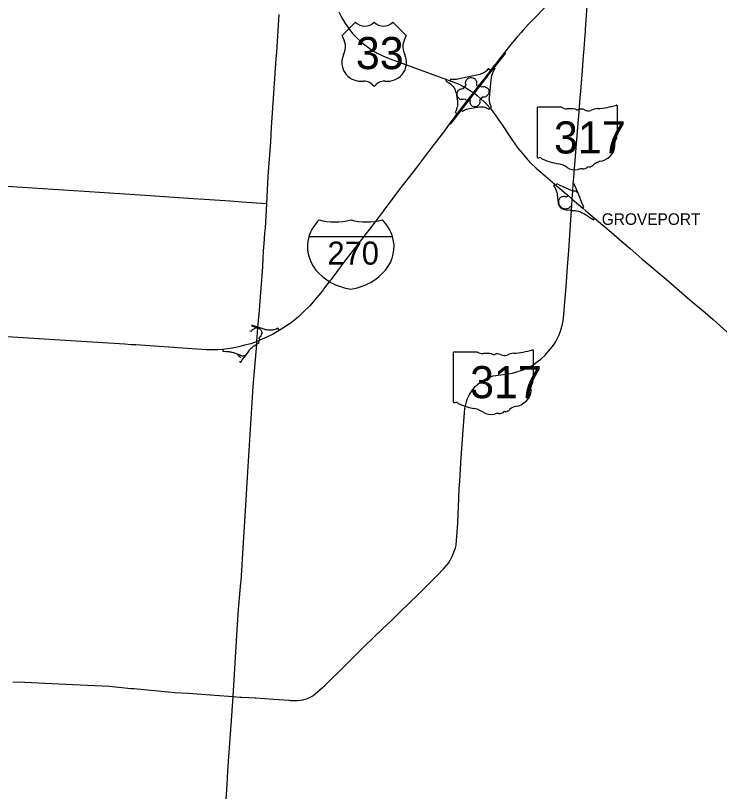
# Model space of a CAD drawing. Extents: x -1146 to -445, y -1283 to -822.
# Drawn here: x -862.8 to -786.6, y -1188.9 to -1104.6 of the extents above; entities that cross this region are included whole.
import ezdxf

# ---------------------------------------------------------------- set-up
doc = ezdxf.new("R2010")
doc.units = 0
for name, color, linetype in [('GM_X_Corporation_Text', 7, 'Continuous'), ('GM_X_Interchange_Ramps', 7, 'Continuous'), ('GM_X_Interstate_Route', 7, 'Continuous'), ('GM_X_Interstate_Shield', 7, 'Continuous'), ('GM_X_State_Route', 7, 'Continuous'), ('GM_X_State_Shield', 7, 'Continuous'), ('GM_X_Township', 7, 'Continuous'), ('GM_X_US_Route', 7, 'Continuous'), ('GM_X_US_Shield', 7, 'Continuous')]:
    doc.layers.add(name, color=color, linetype=linetype)

msp = doc.modelspace()

# ---------------------------------------------------------------- linework, layer by layer
at = {"layer": 'GM_X_Interchange_Ramps'}
for points in [[(-815.755, -1116.238), (-815.666, -1116.305), (-814.538, -1114.844), (-813.657, -1113.702), (-813.113, -1112.993), (-812.492, -1112.192), (-811.272, -1110.612), (-810.936, -1110.185), (-810.719, -1109.91), (-809.747, -1108.674), (-809.865, -1108.581)], [(-811.378, -1110.516), (-811.597, -1110.343), (-811.68, -1110.434), (-811.773, -1110.524), (-811.885, -1110.618), (-811.997, -1110.699), (-812.142, -1110.788), (-812.248, -1110.843), (-812.386, -1110.903), (-812.518, -1110.949), (-812.701, -1110.997), (-814.914, -1111.467), (-815.04, -1111.486), (-815.192, -1111.497), (-815.498, -1111.495), (-815.709, -1111.493), (-815.765, -1111.639)], [(-811.418, -1114.592), (-811.263, -1114.461), (-811.303, -1114.391), (-811.354, -1114.28), (-811.396, -1114.174), (-811.427, -1114.073), (-811.454, -1113.968), (-811.475, -1113.856), (-811.488, -1113.753), (-811.495, -1113.625), (-811.492, -1113.472), (-811.289, -1111.531), (-811.274, -1111.394), (-811.249, -1111.243), (-811.222, -1111.118), (-811.189, -1110.994), (-811.155, -1110.884), (-811.116, -1110.775), (-811.058, -1110.634), (-811.01, -1110.532), (-810.916, -1110.333), (-810.862, -1110.244), (-810.936, -1110.185)], [(-814.183, -1112.324), (-814.011, -1112.128), (-814.044, -1112.02), (-814.059, -1111.93), (-814.06, -1111.832), (-814.044, -1111.731), (-814.007, -1111.624), (-813.963, -1111.546), (-813.887, -1111.453), (-813.811, -1111.388), (-813.721, -1111.336), (-813.64, -1111.304), (-813.55, -1111.284), (-813.431, -1111.279), (-813.291, -1111.304), (-813.202, -1111.34), (-813.116, -1111.391), (-813.036, -1111.461), (-812.979, -1111.529), (-812.935, -1111.601), (-812.895, -1111.699), (-812.875, -1111.788), (-812.869, -1111.883), (-812.893, -1112.116), (-812.721, -1112.254)], [(-816.129, -1111.498), (-816.202, -1111.673), (-816.066, -1111.746), (-815.979, -1111.795), (-815.893, -1111.847), (-815.8, -1111.905), (-815.715, -1111.965), (-815.641, -1112.029), (-815.573, -1112.094), (-815.497, -1112.175), (-815.419, -1112.27), (-815.351, -1112.364), (-815.295, -1112.452), (-815.235, -1112.561), (-815.188, -1112.66), (-815.139, -1112.785), (-815.109, -1112.879), (-815.08, -1112.992), (-815.056, -1113.107), (-815.037, -1113.201), (-815.017, -1113.31), (-814.996, -1113.438), (-814.979, -1113.547), (-814.963, -1113.67), (-814.95, -1113.775), (-814.941, -1113.865), (-814.931, -1113.969), (-814.928, -1114.069), (-814.929, -1114.152), (-814.938, -1114.271), (-814.953, -1114.382), (-814.973, -1114.483), (-814.998, -1114.579), (-815.032, -1114.686), (-815.093, -1114.863), (-815.18, -1115.058), (-814.994, -1115.194)], [(-813.913, -1113.792), (-814.127, -1113.629), (-814.308, -1113.674), (-814.391, -1113.681), (-814.486, -1113.674), (-814.585, -1113.651), (-814.677, -1113.612), (-814.773, -1113.549), (-814.838, -1113.488), (-814.9, -1113.408), (-814.945, -1113.323), (-814.976, -1113.233), (-814.993, -1113.133), (-814.991, -1113.027), (-814.973, -1112.928), (-814.939, -1112.836), (-814.892, -1112.752), (-814.826, -1112.671), (-814.758, -1112.611), (-814.677, -1112.56), (-814.592, -1112.523), (-814.486, -1112.497), (-814.3, -1112.486), (-814.183, -1112.324)], [(-812.492, -1112.192), (-812.373, -1112.287), (-812.212, -1112.247), (-812.116, -1112.241), (-812.021, -1112.25), (-811.895, -1112.287), (-811.783, -1112.35), (-811.717, -1112.405), (-811.659, -1112.469), (-811.602, -1112.56), (-811.557, -1112.674), (-811.538, -1112.79), (-811.541, -1112.895), (-811.56, -1112.99), (-811.595, -1113.082), (-811.649, -1113.173), (-811.709, -1113.243), (-811.794, -1113.313), (-811.879, -1113.361), (-811.99, -1113.399), (-812.092, -1113.414), (-812.255, -1113.412), (-812.399, -1113.583)], [(-812.399, -1113.583), (-812.547, -1113.744), (-812.536, -1113.822), (-812.528, -1113.905), (-812.534, -1113.99), (-812.552, -1114.097), (-812.603, -1114.216), (-812.657, -1114.293), (-812.734, -1114.365), (-812.831, -1114.424), (-812.916, -1114.455), (-813.018, -1114.471), (-813.131, -1114.465), (-813.234, -1114.437), (-813.301, -1114.406), (-813.387, -1114.345), (-813.452, -1114.277), (-813.501, -1114.204), (-813.535, -1114.125), (-813.557, -1114.037), (-813.563, -1113.948), (-813.547, -1113.785), (-813.657, -1113.702)], [(-814.538, -1114.844), (-814.414, -1114.938), (-814.275, -1114.86), (-814.198, -1114.821), (-814.129, -1114.789), (-814.04, -1114.753), (-813.958, -1114.724), (-813.839, -1114.689), (-813.644, -1114.646), (-812.549, -1114.466), (-812.438, -1114.452), (-812.325, -1114.448), (-812.228, -1114.454), (-812.117, -1114.47), (-811.996, -1114.5), (-811.9, -1114.534), (-811.759, -1114.601), (-811.673, -1114.655), (-811.58, -1114.725), (-811.418, -1114.592)], [(-804.392, -1122.842), (-804.539, -1123.004), (-804.438, -1123.143), (-804.379, -1123.238), (-804.322, -1123.343), (-804.282, -1123.428), (-804.245, -1123.519), (-804.211, -1123.62), (-804.184, -1123.719), (-804.157, -1123.85), (-804.14, -1123.983), (-804.046, -1124.892), (-804.014, -1125.012), (-803.975, -1125.104), (-803.932, -1125.182), (-803.868, -1125.273), (-803.788, -1125.36), (-803.723, -1125.416), (-803.643, -1125.471), (-803.562, -1125.516), (-803.489, -1125.546), (-803.394, -1125.574), (-803.306, -1125.589), (-803.188, -1125.608), (-802.71, -1125.654), (-802.61, -1125.661)], [(-802.461, -1123.569), (-802.532, -1123.565), (-803.888, -1122.939), (-804.168, -1122.782), (-804.293, -1122.928)], [(-801.379, -1125.423), (-801.256, -1125.29), (-801.362, -1125.09), (-801.915, -1123.746), (-802.227, -1122.987), (-802.283, -1122.831), (-802.412, -1122.823)], [(-802.579, -1125.253), (-802.714, -1125.243), (-802.762, -1125.309), (-802.825, -1125.374), (-802.892, -1125.426), (-802.96, -1125.465), (-803.026, -1125.494), (-803.091, -1125.513), (-803.182, -1125.528), (-803.269, -1125.53), (-803.354, -1125.52), (-803.446, -1125.495), (-803.593, -1125.416), (-803.694, -1125.346), (-803.78, -1125.265), (-803.856, -1125.167), (-803.904, -1125.083), (-803.937, -1125.007), (-803.969, -1124.899), (-803.985, -1124.789), (-803.986, -1124.674), (-803.964, -1124.552), (-803.934, -1124.475), (-803.898, -1124.409), (-803.853, -1124.348), (-803.778, -1124.274), (-803.703, -1124.221), (-803.614, -1124.179), (-803.528, -1124.154), (-803.443, -1124.143), (-803.347, -1124.146), (-803.267, -1124.161), (-803.205, -1124.181), (-803.117, -1124.22), (-802.965, -1124.065)], [(-801.915, -1123.746), (-801.943, -1123.758), (-801.99, -1123.708), (-802.046, -1123.663), (-802.107, -1123.627), (-802.18, -1123.599), (-802.247, -1123.583), (-802.293, -1123.578), (-802.341, -1123.577), (-802.461, -1123.569)], [(-802.61, -1125.661), (-802.524, -1125.668), (-802.276, -1125.686), (-802.192, -1125.693), (-802.095, -1125.709), (-801.829, -1125.768), (-801.62, -1125.836), (-801.43, -1125.922), (-801.266, -1126.005), (-801.099, -1126.107), (-800.232, -1126.684), (-800.094, -1126.526)], [(-837.429, -1138.702), (-837.259, -1138.761), (-837.184, -1138.657), (-837.116, -1138.572), (-837.048, -1138.518), (-836.988, -1138.48), (-836.874, -1138.422), (-836.762, -1138.398), (-836.668, -1138.392), (-836.545, -1138.413), (-836.465, -1138.435), (-836.346, -1138.499), (-836.277, -1138.566), (-836.224, -1138.636), (-836.188, -1138.703), (-836.158, -1138.778), (-836.136, -1138.877), (-836.131, -1138.975), (-836.146, -1139.089), (-836.179, -1139.189), (-836.221, -1139.269), (-836.295, -1139.354), (-836.359, -1139.413), (-836.429, -1139.466), (-836.326, -1139.733)], [(-837.235, -1138.166), (-837.149, -1138.194), (-836.766, -1138.318), (-836.762, -1138.398)], [(-834.235, -1138.672), (-834.387, -1138.441), (-834.484, -1138.485), (-834.582, -1138.526), (-834.691, -1138.564), (-834.791, -1138.593), (-834.898, -1138.616), (-834.988, -1138.631), (-835.104, -1138.644), (-835.227, -1138.65), (-835.349, -1138.647), (-835.481, -1138.635), (-835.604, -1138.616), (-835.726, -1138.588), (-835.875, -1138.542), (-836.547, -1138.324), (-837.13, -1138.136), (-837.211, -1138.107)], [(-838.578, -1142.049), (-838.412, -1142.112), (-838.338, -1141.989), (-838.246, -1141.854), (-838.074, -1141.628), (-837.868, -1141.393), (-837.47, -1140.809), (-837.413, -1140.744), (-837.336, -1140.663), (-837.259, -1140.586), (-837.185, -1140.517), (-837.1, -1140.442), (-837.023, -1140.379), (-836.95, -1140.322), (-836.854, -1140.252), (-836.68, -1140.139), (-836.605, -1140.094), (-836.514, -1140.044), (-836.414, -1139.993), (-836.489, -1139.8)], [(-840.346, -1140.727), (-840.33, -1140.917), (-839.945, -1140.936), (-839.853, -1140.941), (-839.754, -1140.949), (-839.658, -1140.961), (-839.576, -1140.974), (-839.484, -1140.991), (-839.409, -1141.008), (-839.318, -1141.032), (-839.198, -1141.066), (-839.089, -1141.102), (-838.984, -1141.137), (-838.844, -1141.205), (-838.793, -1141.229), (-838.746, -1141.261), (-838.71, -1141.295), (-838.68, -1141.326), (-838.649, -1141.37), (-838.621, -1141.424), (-838.595, -1141.477), (-838.409, -1141.553)], [(-838.844, -1141.205), (-838.838, -1141.187), (-838.496, -1141.298), (-838.347, -1141.377)], [(-838.347, -1141.377), (-838.255, -1141.403), (-838.161, -1141.426), (-838.097, -1141.428), (-838.028, -1141.417), (-837.96, -1141.396), (-837.895, -1141.36), (-837.868, -1141.393)]]:
    msp.add_lwpolyline(points, dxfattribs=at)
at = {"layer": 'GM_X_Interstate_Route'}
for points in [[(-802.193, -1100.582), (-803.442, -1101.758), (-804.597, -1102.868), (-805.506, -1103.728), (-806.515, -1104.793), (-807.247, -1105.509), (-807.849, -1106.161), (-808.05, -1106.398)], [(-808.05, -1106.398), (-808.433, -1106.851), (-809.294, -1107.905), (-809.865, -1108.581)], [(-809.865, -1108.581), (-810.411, -1109.26), (-810.841, -1109.83), (-810.994, -1110.026)], [(-810.994, -1110.026), (-811.378, -1110.516), (-812.094, -1111.457), (-812.721, -1112.254), (-813.213, -1112.917)], [(-813.213, -1112.917), (-813.913, -1113.792), (-814.994, -1115.194), (-815.755, -1116.238)], [(-815.755, -1116.238), (-816.352, -1117.052), (-818.094, -1119.304), (-819.489, -1121.166), (-821.329, -1123.527), (-822.571, -1125.184)], [(-822.96, -1125.704), (-823.204, -1126.03), (-823.963, -1127.051), (-825.848, -1129.473), (-827.14, -1131.139), (-828.438, -1132.89), (-828.662, -1133.186), (-828.711, -1133.251)], [(-822.571, -1125.184), (-822.957, -1125.7), (-822.96, -1125.704)], [(-828.711, -1133.251), (-829.436, -1134.207), (-829.496, -1134.286)], [(-829.496, -1134.286), (-829.599, -1134.422), (-830.94, -1135.992), (-831.667, -1136.728), (-832.098, -1137.141), (-832.123, -1137.163)], [(-850.255, -1140.217), (-850.957, -1140.159), (-856.794, -1139.812), (-863.126, -1139.382), (-866.131, -1139.196), (-870.172, -1138.941), (-873.251, -1138.719), (-876.652, -1138.518), (-877.807, -1138.452), (-880.683, -1138.232), (-881.301, -1138.185), (-883.025, -1138.058), (-883.999, -1137.894), (-884.369, -1137.831), (-885.679, -1137.562)], [(-832.123, -1137.163), (-832.547, -1137.535), (-833.061, -1137.911), (-834.235, -1138.672), (-834.976, -1139.11), (-835.825, -1139.506), (-836.326, -1139.733), (-836.489, -1139.8), (-836.654, -1139.868), (-836.712, -1139.892)], [(-836.712, -1139.892), (-836.732, -1139.9), (-837.318, -1140.109), (-837.985, -1140.276)], [(-837.985, -1140.276), (-838.609, -1140.436), (-839.313, -1140.584), (-840.346, -1140.727), (-840.931, -1140.762), (-842.101, -1140.781), (-843.679, -1140.66), (-849.762, -1140.246), (-850.126, -1140.227), (-850.255, -1140.217)]]:
    msp.add_lwpolyline(points, dxfattribs=at)
at = {"layer": 'GM_X_Interstate_Shield'}
msp.add_line((-821.965, -1128.54), (-831.03, -1128.54), dxfattribs=at)
msp.add_line((-821.965, -1128.54), (-831.03, -1128.54), dxfattribs=at)
for centre, start_param, end_param in [((-825.325, -1129.611), 2.47259, 2.911027), ((-828.21, -1122.221), 4.415841, 5.008937), ((-824.785, -1122.221), 4.415841, 5.008937), ((-827.669, -1129.611), 0.230566, 0.669003), ((-825.325, -1129.611), 2.911027, 4.511031), ((-827.669, -1129.611), 4.913747, 6.513751)]:
    msp.add_ellipse(centre, major_axis=(5.859, 0), ratio=0.8, start_param=start_param, end_param=end_param, dxfattribs=at)
at = {"layer": 'GM_X_State_Route'}
for points in [[(-801.078, -1106.07), (-800.916, -1103.575)], [(-801.64, -1113.153), (-801.462, -1111.026), (-801.296, -1108.938), (-801.246, -1108.174), (-801.205, -1107.671), (-801.17, -1107.183), (-801.13, -1106.705), (-801.09, -1106.252), (-801.078, -1106.07)], [(-801.662, -1113.415), (-801.64, -1113.153)], [(-802.351, -1122.148), (-802.26, -1121.145), (-801.882, -1116.235), (-801.775, -1114.99), (-801.7, -1113.94)], [(-801.7, -1113.94), (-801.668, -1113.485), (-801.662, -1113.415)], [(-802.518, -1124.458), (-802.461, -1123.569), (-802.412, -1122.823), (-802.375, -1122.418)], [(-802.375, -1122.418), (-802.351, -1122.148)], [(-802.6, -1125.525), (-802.579, -1125.253), (-802.518, -1124.458)], [(-802.682, -1126.685), (-802.61, -1125.661), (-802.6, -1125.525)], [(-813.98, -1146.405), (-813.875, -1146.045), (-813.695, -1145.664), (-813.404, -1145.202), (-813.033, -1144.741), (-812.513, -1144.292), (-812.242, -1144.114), (-811.859, -1143.9), (-811.37, -1143.687), (-811.094, -1143.594), (-810.795, -1143.534), (-809.45, -1143.376), (-808.979, -1143.286), (-808.618, -1143.206), (-807.945, -1142.985), (-807.363, -1142.724), (-806.802, -1142.413), (-806.276, -1142.051), (-805.921, -1141.78), (-805.455, -1141.346), (-805.086, -1140.913), (-804.666, -1140.394), (-804.329, -1139.929), (-804.142, -1139.573), (-803.947, -1139.153), (-803.779, -1138.732), (-803.569, -1137.994), (-803.498, -1137.649), (-803.463, -1137.296), (-803.381, -1136.509), (-803.275, -1135.158), (-803.193, -1133.937), (-803.017, -1131.787), (-802.886, -1130.019), (-802.682, -1126.685)], [(-814.698, -1154.996), (-814.567, -1153.003), (-814.354, -1149.928), (-814.138, -1147.123), (-814.019, -1146.536), (-813.98, -1146.405)], [(-814.8, -1156.969), (-814.783, -1156.699), (-814.756, -1155.835), (-814.698, -1154.996)], [(-818.125, -1166.176), (-817.157, -1165.201), (-816.425, -1164.446), (-815.916, -1163.855), (-815.573, -1163.295), (-815.393, -1162.846), (-815.168, -1162.191), (-815.102, -1161.908), (-815.036, -1161.403), (-814.915, -1159.555), (-814.841, -1157.616), (-814.804, -1157.027), (-814.8, -1156.969)], [(-818.597, -1166.648), (-818.404, -1166.456), (-818.125, -1166.176)], [(-833.008, -1178.725), (-832.309, -1178.745), (-831.977, -1178.713), (-831.672, -1178.66), (-831.42, -1178.591), (-831.172, -1178.515), (-830.874, -1178.385), (-830.592, -1178.229), (-829.3, -1177.117), (-827.136, -1174.979), (-825.056, -1172.91), (-823.028, -1170.952), (-822.152, -1170.134), (-821.025, -1169.034), (-819.282, -1167.325), (-818.597, -1166.648)], [(-863.071, -1176.712), (-861.792, -1176.766), (-857.366, -1176.969)], [(-857.366, -1176.969), (-852.602, -1177.188), (-850.291, -1177.424), (-849.99, -1177.453)], [(-849.99, -1177.453), (-845.915, -1177.843), (-845.578, -1177.864), (-845.523, -1177.867)], [(-845.523, -1177.867), (-844.046, -1177.957), (-841.213, -1178.153), (-841.203, -1178.154)], [(-841.203, -1178.154), (-839.213, -1178.312), (-838.456, -1178.365), (-838.316, -1178.37)], [(-838.316, -1178.37), (-837.539, -1178.403), (-836.852, -1178.459), (-836.779, -1178.463)], [(-836.779, -1178.463), (-834.815, -1178.592), (-833.133, -1178.721), (-833.008, -1178.725)]]:
    msp.add_lwpolyline(points, dxfattribs=at)
at = {"layer": 'GM_X_State_Shield'}
for p, q in [((-806.322, -1114.597), (-806.322, -1119.88)), ((-803.689, -1114.506), (-806.237, -1114.506)), ((-797.621, -1117.139), (-797.621, -1114.375)), ((-797.622, -1117.138), (-797.621, -1117.139)), ((-806.698, -1143.639), (-806.698, -1140.875)), ((-815.399, -1141.097), (-815.399, -1146.38)), ((-812.766, -1141.006), (-815.314, -1141.006)), ((-806.699, -1143.638), (-806.698, -1143.639))]:
    msp.add_line(p, q, dxfattribs=at)
for centre, major_axis, start_param, end_param in [((-806.223, -1114.586), (0.101, 0), 1.712693, 3.28349), ((-803.082, -1113.893), (0.978, 0), 4.042523, 4.731795), ((-802.758, -1117.472), (3.51, 0), 1.404758, 1.657858), ((-801.961, -1114.559), (0.282, 0), 3.836095, 5.185415), ((-801.547, -1115.169), (0.586, 0), 0.950623, 2.079405), ((-800.79, -1114.332), (0.705, 0), 4.081561, 5.145723), ((-799.544, -1116.12), (1.856, 0), 1.699011, 2.107814), ((-800.721, -1107.304), (9.227, 0), 4.814394, 5.042369), ((-797.718, -1114.364), (0.0969, 0), 6.141152, 7.989035), ((-797.644, -1117.342), (0.15, 0), 1.883978, 3.671073), ((-797.725, -1117.15), (0.104, 0), 5.05454, 6.418171), ((-797.274, -1118.296), (0.655, 0), 2.387724, 3.262537), ((-798.597, -1117.691), (0.9, 0), 5.934695, 6.695948), ((-800.204, -1118.647), (2.308, 0), 5.101752, 6.440018), ((-806.222, -1119.892), (0.102, 0), 3.00124, 4.508301), ((-806.206, -1119.351), (0.776, 0), 4.665946, 4.897461), ((-806.048, -1120.185), (0.28, 0), 0.519207, 1.627899), ((-802.515, -1115.438), (6.663, 0), 4.195997, 4.488961), ((-804.501, -1122.254), (2.085, 0), 0.823519, 1.323587), ((-800.832, -1120.392), (0.746, 0), 4.937069, 5.64225), ((-799.231, -1121.364), (1.264, 0), 1.647645, 2.488434), ((-802.246, -1120.211), (1.323, 0), 4.026481, 4.996735), ((-801.482, -1122.038), (1.087, 0), 1.495662, 1.94098), ((-801.385, -1120.607), (0.705, 0), 4.691044, 5.507374), ((-800.748, -1121.119), (0.198, 0), 1.147584, 2.315152), ((-809.798, -1133.803), (9.227, 0), 4.814394, 5.042369), ((-806.795, -1140.864), (0.0969, 0), 6.141152, 7.989035), ((-815.3, -1141.086), (0.101, 0), 1.712693, 3.28349), ((-812.159, -1140.393), (0.978, 0), 4.042523, 4.731795), ((-811.835, -1143.972), (3.51, 0), 1.404758, 1.657858), ((-811.038, -1141.058), (0.282, 0), 3.836095, 5.185415), ((-810.624, -1141.669), (0.586, 0), 0.950623, 2.079405), ((-809.867, -1140.831), (0.705, 0), 4.081561, 5.145723), ((-808.621, -1142.62), (1.856, 0), 1.699011, 2.107814), ((-806.721, -1143.842), (0.15, 0), 1.883978, 3.671073), ((-807.674, -1144.191), (0.9, 0), 5.934695, 6.695948), ((-806.802, -1143.649), (0.104, 0), 5.05454, 6.418171), ((-809.281, -1145.147), (2.308, 0), 5.101752, 6.440018), ((-806.351, -1144.795), (0.655, 0), 2.387724, 3.262537), ((-815.299, -1146.392), (0.102, 0), 3.00124, 4.508301), ((-815.283, -1145.851), (0.776, 0), 4.665946, 4.897461), ((-815.125, -1146.685), (0.28, 0), 0.519207, 1.627899), ((-811.592, -1141.938), (6.663, 0), 4.195997, 4.488961), ((-808.308, -1147.863), (1.264, 0), 1.647645, 2.488434), ((-813.578, -1148.754), (2.085, 0), 0.823519, 1.323587), ((-811.323, -1146.711), (1.323, 0), 4.026481, 4.996735), ((-810.559, -1148.538), (1.087, 0), 1.495662, 1.94098), ((-810.462, -1147.107), (0.705, 0), 4.691044, 5.507374), ((-809.825, -1147.618), (0.198, 0), 1.147584, 2.315152), ((-809.909, -1146.892), (0.746, 0), 4.937069, 5.64225)]:
    msp.add_ellipse(centre, major_axis=major_axis, ratio=0.8, start_param=start_param, end_param=end_param, dxfattribs=at)
at = {"layer": 'GM_X_Township'}
for points in [[(-839.986, -1189.404), (-839.888, -1187.914), (-839.788, -1186.397), (-839.683, -1184.799), (-839.589, -1183.374), (-839.458, -1181.394), (-839.213, -1178.312), (-838.817, -1171.67), (-838.631, -1168.836), (-838.386, -1166.005), (-838.375, -1165.843), (-838.093, -1161.622), (-837.883, -1158.186), (-837.65, -1153.964), (-837.042, -1144.742), (-836.68, -1140.139), (-836.654, -1139.868), (-836.545, -1138.413), (-836.547, -1138.324), (-836.376, -1136.537), (-836.345, -1135.972), (-836.011, -1131.781), (-835.936, -1130.045), (-835.887, -1129.24), (-835.789, -1128.143), (-835.735, -1127.555), (-835.589, -1125.008), (-835.585, -1124.955), (-835.431, -1121.964), (-835.159, -1118.245), (-835.078, -1116.687), (-834.556, -1109.269), (-834.503, -1108.493), (-834.261, -1104.464)], [(-835.589, -1125.008), (-835.585, -1124.955), (-835.644, -1124.951), (-838.263, -1124.769), (-839.555, -1124.672), (-842.354, -1124.475), (-843.569, -1124.413), (-848.745, -1124.067), (-855.341, -1123.619), (-862.055, -1123.177), (-864.742, -1123.001), (-866.693, -1122.873), (-866.806, -1122.867), (-870.047, -1122.655), (-871.799, -1122.523), (-874.423, -1122.339), (-875.436, -1122.275), (-877.054, -1122.178), (-878.503, -1122.082), (-879.46, -1122.01), (-882.142, -1121.871), (-887.957, -1121.659)]]:
    msp.add_lwpolyline(points, dxfattribs=at)
at = {"layer": 'GM_X_US_Route'}
for points in [[(-827.794, -1104.163), (-827.57, -1104.623), (-827.356, -1105.011), (-827.11, -1105.419), (-826.741, -1105.935), (-826.253, -1106.547), (-825.856, -1106.966), (-825.472, -1107.333), (-824.986, -1107.748), (-824.239, -1108.279), (-823.621, -1108.644), (-823.022, -1108.945), (-822.531, -1109.149), (-821.937, -1109.377), (-819.762, -1110.169), (-817.898, -1110.853), (-816.129, -1111.498), (-815.765, -1111.639), (-815.622, -1111.686), (-815.15, -1111.861), (-814.875, -1111.977), (-814.595, -1112.11), (-814.35, -1112.235), (-814.183, -1112.324), (-814.031, -1112.413), (-813.667, -1112.629), (-813.426, -1112.781)], [(-813.426, -1112.781), (-813.213, -1112.917), (-813.113, -1112.993), (-812.813, -1113.234), (-812.399, -1113.583), (-812.052, -1113.912), (-811.739, -1114.24), (-811.418, -1114.592), (-811.061, -1115.059), (-810.776, -1115.436), (-810.031, -1116.534), (-809.195, -1117.772), (-808.403, -1118.918), (-807.918, -1119.523), (-807.405, -1120.12), (-806.967, -1120.58), (-806.412, -1121.111), (-804.392, -1122.842), (-804.293, -1122.928), (-802.965, -1124.065), (-802.518, -1124.458)], [(-802.518, -1124.458), (-801.379, -1125.423), (-801.036, -1125.717)], [(-801.036, -1125.717), (-800.094, -1126.526), (-799.892, -1126.698)], [(-799.892, -1126.698), (-798.321, -1128.034), (-797.134, -1129.056), (-796.265, -1129.799)], [(-796.265, -1129.799), (-794.971, -1130.905), (-792.364, -1133.132), (-790.065, -1135.107), (-789.806, -1135.34), (-789.528, -1135.577), (-788.145, -1136.739), (-787.251, -1137.502), (-785.769, -1138.82), (-785.123, -1139.466), (-784.543, -1140.047), (-783.239, -1141.424), (-782.129, -1142.603), (-781.234, -1143.468), (-780.589, -1143.995), (-780.079, -1144.379), (-779.517, -1144.768), (-778.842, -1145.18), (-774.819, -1147.381), (-770.552, -1149.725), (-770.424, -1149.795)]]:
    msp.add_lwpolyline(points, dxfattribs=at)
at = {"layer": 'GM_X_US_Shield'}
for p, q in [((-825.992, -1105.301), (-827.442, -1106.751)), ((-820.481, -1106.751), (-821.932, -1105.301)), ((-825.412, -1111.681), (-825.122, -1111.681)), ((-822.802, -1111.681), (-822.512, -1111.681))]:
    msp.add_line(p, q, dxfattribs=at)
for centre, radius, start, end in [((-824.977, -1104.265), 1.45, 225.573, 314.427), ((-822.947, -1104.265), 1.45, 225.573, 314.427), ((-829.105, -1107.915), 2.03, 334.54712, 35.00093), ((-818.818, -1107.915), 2.03, 144.99907, 205.45288), ((-825.435, -1109.651), 2.03, 154.83192, 270.63826), ((-822.489, -1109.651), 2.03, 269.36174, 25.16808), ((-825.122, -1113.132), 1.45, 36.8699, 90), ((-822.802, -1113.132), 1.45, 90, 143.1301)]:
    msp.add_arc(centre, radius, start, end, dxfattribs=at)

# ---------------------------------------------------------------- texts
at = {"layer": 'GM_X_Corporation_Text'}
msp.add_text('GROVEPORT', height=1.25, rotation=0.00001, dxfattribs=at).set_placement((-799.322, -1127.239))
at = {"layer": 'GM_X_Interstate_Shield'}
msp.add_text('270', height=2.5, dxfattribs=at).set_placement((-829.022, -1131.548))
at = {"layer": 'GM_X_State_Shield'}
for p in [(-804.498, -1119.508), (-813.575, -1146.008)]:
    msp.add_text('317', height=3.4805, dxfattribs=at).set_placement(p)
at = {"layer": 'GM_X_US_Shield'}
msp.add_text('33', height=3.4805, dxfattribs=at).set_placement((-825.943, -1110.376))

doc.saveas('drawing.dxf')
